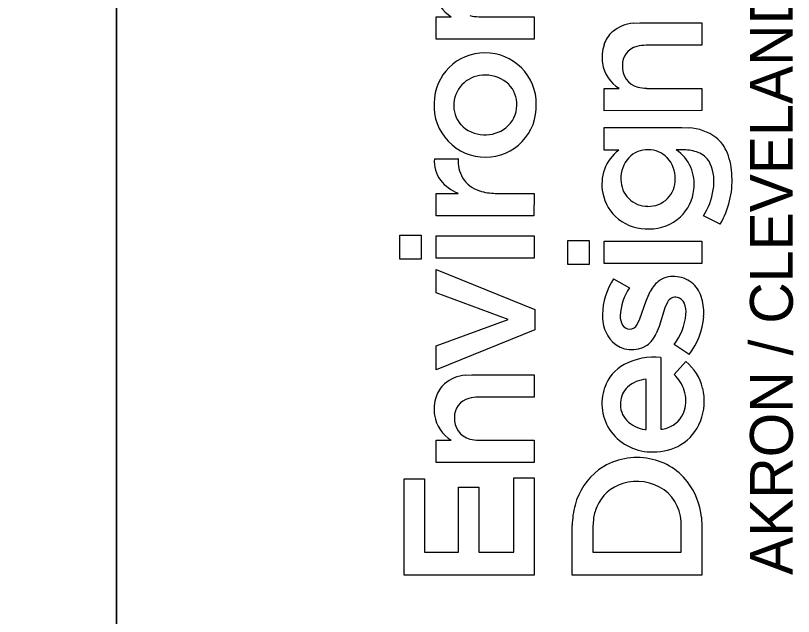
# Model space of a CAD drawing. Extents: x -0.1 to 34, y 0 to 22.
# Drawn here: x 31.866 to 32.901, y 2.583 to 3.382 of the extents above; entities that cross this region are included whole.
import ezdxf

# ---------------------------------------------------------------- set-up
doc = ezdxf.new("R2010")
doc.units = 0
for name, color, linetype in [('SH_Border', 7, 'Continuous'), ('SH_Data', 7, 'Continuous'), ('SH_Text', 7, 'Continuous')]:
    doc.layers.add(name, color=color, linetype=linetype)

msp = doc.modelspace()

# ---------------------------------------------------------------- linework, layer by layer
at = {"layer": 'SH_Border'}
msp.add_line((32, 0.5), (32, 21.5), dxfattribs=at)
at = {"layer": 'SH_Data'}
for p, q in [((32.4254, 3.3509), (32.4254, 3.3807)), ((32.4254, 3.3807), (32.4455, 3.3807)), ((32.4822, 3.3807), (32.5557, 3.3807)), ((32.5557, 3.3807), (32.5557, 3.351)), ((32.6878, 3.3722), (32.6963, 3.3727)), ((32.6963, 3.3727), (32.7792, 3.3727)), ((32.7792, 3.3727), (32.7792, 3.3429)), ((32.5557, 3.351), (32.4254, 3.3509)), ((32.7792, 3.3429), (32.7048, 3.3428)), ((32.6489, 3.2557), (32.6489, 3.2855)), ((32.6489, 3.2855), (32.669, 3.2855)), ((32.7057, 3.2855), (32.7791, 3.2855)), ((32.7791, 3.2855), (32.7792, 3.2558)), ((32.7792, 3.2558), (32.6489, 3.2557)), ((32.6489, 3.2034), (32.6489, 3.2332)), ((32.6489, 3.2332), (32.7524, 3.2332)), ((32.7524, 3.2332), (32.7619, 3.2329)), ((32.6684, 3.2034), (32.6489, 3.2034)), ((32.7576, 3.2036), (32.7449, 3.2036)), ((32.423, 3.1919), (32.4545, 3.1919)), ((32.4254, 3.1159), (32.4254, 3.1458)), ((32.4254, 3.1458), (32.4547, 3.1458)), ((32.5041, 3.1458), (32.5557, 3.1457)), ((32.5557, 3.1457), (32.5556, 3.1159)), ((32.5556, 3.1159), (32.4254, 3.1159)), ((32.8036, 3.1049), (32.7812, 3.116)), ((32.3771, 3.0582), (32.3771, 3.0903)), ((32.3771, 3.0903), (32.4054, 3.0903)), ((32.4054, 3.0903), (32.4054, 3.0582)), ((32.4254, 3.0594), (32.4254, 3.0893)), ((32.4254, 3.0893), (32.5557, 3.0893)), ((32.5557, 3.0893), (32.5557, 3.0594)), ((32.6005, 3.0511), (32.6005, 3.0832)), ((32.6005, 3.0832), (32.6289, 3.0832)), ((32.6289, 3.0832), (32.6289, 3.0511)), ((32.6489, 3.0523), (32.6489, 3.0822)), ((32.6489, 3.0822), (32.7792, 3.0822)), ((32.7792, 3.0822), (32.7792, 3.0523)), ((32.4054, 3.0582), (32.3771, 3.0582)), ((32.5557, 3.0594), (32.4254, 3.0594)), ((32.4254, 3.0133), (32.4254, 3.0446)), ((32.4254, 3.0446), (32.5567, 2.9913)), ((32.6289, 3.0511), (32.6005, 3.0511)), ((32.7792, 3.0523), (32.6489, 3.0523)), ((32.6615, 3.0321), (32.6827, 3.0203)), ((32.5212, 2.978), (32.4254, 3.0133)), ((32.7048, 3.0026), (32.7104, 3.0153)), ((32.6967, 2.9787), (32.7048, 3.0026)), ((32.7298, 2.9933), (32.7221, 2.9688)), ((32.7334, 3.001), (32.7298, 2.9933)), ((32.5567, 2.9913), (32.5567, 2.9644)), ((32.4254, 2.9429), (32.5212, 2.978)), ((32.693, 2.9712), (32.6967, 2.9787)), ((32.5567, 2.9644), (32.4254, 2.9109)), ((32.7221, 2.9688), (32.7182, 2.9592)), ((32.4254, 2.9109), (32.4254, 2.9429)), ((32.7621, 2.9314), (32.742, 2.9447)), ((32.7245, 2.9275), (32.7246, 2.8319)), ((32.7423, 2.9046), (32.7577, 2.922)), ((32.4644, 2.904), (32.4729, 2.9044)), ((32.4729, 2.9044), (32.5557, 2.9044)), ((32.5557, 2.9044), (32.5557, 2.8746)), ((32.7049, 2.8318), (32.7049, 2.8983)), ((32.5557, 2.8746), (32.4814, 2.8746)), ((32.7036, 2.8317), (32.7049, 2.8318)), ((32.4254, 2.7875), (32.4254, 2.8173)), ((32.4254, 2.8173), (32.4455, 2.8173)), ((32.4822, 2.8173), (32.5557, 2.8173)), ((32.5557, 2.8173), (32.5557, 2.7876)), ((32.5557, 2.7876), (32.4254, 2.7875)), ((32.383, 2.6379), (32.383, 2.766)), ((32.383, 2.766), (32.4101, 2.766)), ((32.4101, 2.766), (32.4101, 2.6683)), ((32.5286, 2.6683), (32.5286, 2.7672)), ((32.5286, 2.7672), (32.5557, 2.7672)), ((32.5557, 2.7672), (32.5557, 2.6379)), ((32.455, 2.6683), (32.455, 2.7549)), ((32.455, 2.7549), (32.4822, 2.7549)), ((32.4822, 2.7549), (32.4822, 2.6683)), ((32.7785, 2.715), (32.7792, 2.7021)), ((32.6064, 2.638), (32.6064, 2.704)), ((32.6347, 2.7118), (32.6341, 2.7023)), ((32.6341, 2.7023), (32.6341, 2.6684)), ((32.7515, 2.6683), (32.7515, 2.7024)), ((32.7792, 2.7021), (32.7792, 2.638)), ((32.4101, 2.6683), (32.455, 2.6683)), ((32.4822, 2.6683), (32.5286, 2.6683)), ((32.6341, 2.6684), (32.7515, 2.6683)), ((32.5557, 2.6379), (32.383, 2.6379)), ((32.7792, 2.638), (32.6064, 2.638))]:
    msp.add_line(p, q, dxfattribs=at)
for points in [[(32.4254, 3.3509), (32.4254, 3.3807), (32.4455, 3.3807)], [(32.4822, 3.3807), (32.5557, 3.3807), (32.5557, 3.351), (32.4254, 3.3509)], [(32.6878, 3.3722), (32.6963, 3.3727), (32.7792, 3.3727), (32.7792, 3.3429), (32.7048, 3.3428)], [(32.6489, 3.2557), (32.6489, 3.2855), (32.669, 3.2855)], [(32.7057, 3.2855), (32.7791, 3.2855), (32.7792, 3.2558), (32.6489, 3.2557)], [(32.6684, 3.2034), (32.6489, 3.2034), (32.6489, 3.2332), (32.7524, 3.2332), (32.7619, 3.2329)], [(32.7576, 3.2036), (32.7449, 3.2036)], [(32.423, 3.1919), (32.4545, 3.1919)], [(32.4254, 3.1159), (32.4254, 3.1458), (32.4547, 3.1458)], [(32.5041, 3.1458), (32.5557, 3.1457), (32.5556, 3.1159), (32.4254, 3.1159)], [(32.8036, 3.1049), (32.7812, 3.116)], [(32.6615, 3.0321), (32.6827, 3.0203)], [(32.693, 2.9712), (32.6967, 2.9787), (32.7048, 3.0026), (32.7104, 3.0153)], [(32.7334, 3.001), (32.7298, 2.9933), (32.7221, 2.9688), (32.7182, 2.9592)], [(32.7621, 2.9314), (32.742, 2.9447)], [(32.7245, 2.9275), (32.7246, 2.8319)], [(32.7423, 2.9046), (32.7577, 2.922)], [(32.4644, 2.904), (32.4729, 2.9044), (32.5557, 2.9044), (32.5557, 2.8746), (32.4814, 2.8746)], [(32.7036, 2.8317), (32.7049, 2.8318), (32.7049, 2.8983)], [(32.4254, 2.7875), (32.4254, 2.8173), (32.4455, 2.8173)], [(32.4822, 2.8173), (32.5557, 2.8173), (32.5557, 2.7876), (32.4254, 2.7875)], [(32.7785, 2.715), (32.7792, 2.7021), (32.7792, 2.638), (32.6064, 2.638)], [(32.6064, 2.638), (32.6064, 2.704)], [(32.6347, 2.7118), (32.6341, 2.7023), (32.6341, 2.6684), (32.7515, 2.6683), (32.7515, 2.7024)]]:
    msp.add_lwpolyline(points, dxfattribs=at)
for points in [[(32.3771, 3.0582), (32.3771, 3.0903), (32.4054, 3.0903), (32.4054, 3.0582)], [(32.4254, 3.0594), (32.4254, 3.0893), (32.5557, 3.0893), (32.5557, 3.0594)], [(32.6005, 3.0511), (32.6005, 3.0832), (32.6289, 3.0832), (32.6289, 3.0511)], [(32.6489, 3.0523), (32.6489, 3.0822), (32.7792, 3.0822), (32.7792, 3.0523)], [(32.4254, 2.9109), (32.4254, 2.9429), (32.5212, 2.978), (32.4254, 3.0133), (32.4254, 3.0446), (32.5567, 2.9913), (32.5567, 2.9644)], [(32.383, 2.6379), (32.383, 2.766), (32.4101, 2.766), (32.4101, 2.6683), (32.455, 2.6683), (32.455, 2.7549), (32.4822, 2.7549), (32.4822, 2.6683), (32.5286, 2.6683), (32.5286, 2.7672), (32.5557, 2.7672), (32.5557, 2.6379)]]:
    msp.add_lwpolyline(points, close=True, dxfattribs=at)
for centre, radius, start, end in [((32.4703, 3.4214), 0.0476, 188.9646, 238.6987), ((32.4703, 3.4214), 0.0476, 188.9646, 238.6987), ((32.4818, 3.4229), 0.0421, 254.0891, 270.5284), ((32.4818, 3.4229), 0.0421, 254.0891, 270.5284), ((32.6922, 3.3225), 0.0499, 94.9706, 130.2248), ((32.6922, 3.3225), 0.0499, 94.9706, 130.2248), ((32.6869, 3.3309), 0.0402, 132.2238, 161.6823), ((32.6869, 3.3309), 0.0402, 132.2238, 161.6823), ((32.7022, 3.3264), 0.056, 162.274, 187.7917), ((32.7022, 3.3264), 0.056, 162.274, 187.7917), ((32.6983, 3.3169), 0.025, 103.6868, 182.214), ((32.6983, 3.3169), 0.025, 103.6868, 182.214), ((32.7045, 3.2968), 0.046, 89.6051, 105.3303), ((32.7045, 3.2968), 0.046, 89.6051, 105.3303), ((32.4901, 3.2654), 0.0674, 89.8476, 179.6405), ((32.4901, 3.2654), 0.0674, 89.8476, 179.6405), ((32.4906, 3.2647), 0.0681, 359.5401, 90.2114), ((32.4906, 3.2647), 0.0681, 359.5401, 90.2114), ((32.6937, 3.3262), 0.0476, 188.9646, 238.6987), ((32.6937, 3.3262), 0.0476, 188.9646, 238.6987), ((32.7008, 3.3138), 0.0276, 175.5844, 255.1382), ((32.7008, 3.3138), 0.0276, 175.5844, 255.1382), ((32.4892, 3.2626), 0.0404, 87.0481, 175.5726), ((32.4892, 3.2626), 0.0404, 87.0481, 175.5726), ((32.492, 3.26), 0.043, 45.8426, 90.9801), ((32.492, 3.26), 0.043, 45.8426, 90.9801), ((32.4946, 3.2642), 0.0382, 357.8857, 44.159), ((32.4946, 3.2642), 0.0382, 357.8857, 44.159), ((32.7053, 3.3277), 0.0421, 254.0891, 270.5284), ((32.7053, 3.3277), 0.0421, 254.0891, 270.5284), ((32.4908, 3.2621), 0.0682, 176.8344, 270.4038), ((32.4908, 3.2621), 0.0682, 176.8344, 270.4038), ((32.4873, 3.2625), 0.0385, 175.1538, 221.1471), ((32.4873, 3.2625), 0.0385, 175.1538, 221.1471), ((32.4912, 3.2614), 0.0675, 270.0624, 2.3776), ((32.4912, 3.2614), 0.0675, 270.0624, 2.3776), ((32.4945, 3.2632), 0.0383, 308.2894, 359.4347), ((32.4945, 3.2632), 0.0383, 308.2894, 359.4347), ((32.4892, 3.2661), 0.0423, 223.0999, 268.8089), ((32.4892, 3.2661), 0.0423, 223.0999, 268.8089), ((32.491, 3.2679), 0.0442, 266.5651, 308.0608), ((32.491, 3.2679), 0.0442, 266.5651, 308.0608), ((32.7591, 3.1679), 0.065, 53.4034, 87.4906), ((32.7591, 3.1679), 0.065, 53.4034, 87.4906), ((32.7652, 3.1804), 0.0514, 21.6075, 50.5577), ((32.7652, 3.1804), 0.0514, 21.6075, 50.5577), ((32.7029, 3.1581), 0.0569, 127.3748, 192.2247), ((32.7029, 3.1581), 0.0569, 127.3748, 192.2247), ((32.7069, 3.1693), 0.0346, 88.473, 136.4256), ((32.7069, 3.1693), 0.0346, 88.473, 136.4256), ((32.7081, 3.1696), 0.0342, 44.2719, 90.4762), ((32.7081, 3.1696), 0.0342, 44.2719, 90.4762), ((32.7142, 3.1583), 0.0547, 352.1125, 55.923), ((32.7142, 3.1583), 0.0547, 352.1125, 55.923), ((32.7567, 3.1572), 0.0463, 65.0169, 88.8011), ((32.7567, 3.1572), 0.0463, 65.0169, 88.8011), ((32.7626, 3.1716), 0.0309, 26.2681, 63.803), ((32.7626, 3.1716), 0.0309, 26.2681, 63.803), ((32.7307, 3.1671), 0.0884, 1.1514, 21.3627), ((32.7307, 3.1671), 0.0884, 1.1514, 21.3627), ((32.4662, 3.1888), 0.0433, 175.8731, 216.3475), ((32.4662, 3.1888), 0.0433, 175.8731, 216.3475), ((32.5009, 3.1895), 0.0464, 176.9688, 209.6064), ((32.5009, 3.1895), 0.0464, 176.9688, 209.6064), ((32.7114, 3.166), 0.0401, 137.4674, 182.3324), ((32.7114, 3.166), 0.0401, 137.4674, 182.3324), ((32.7037, 3.166), 0.04, 358.5714, 43.5376), ((32.7037, 3.166), 0.04, 358.5714, 43.5376), ((32.7357, 3.1615), 0.0595, 349.3073, 23.4307), ((32.7357, 3.1615), 0.0595, 349.3073, 23.4307), ((32.7054, 3.1624), 0.1138, 329.6388, 3.26), ((32.7054, 3.1624), 0.1138, 329.6388, 3.26), ((32.4747, 3.1972), 0.0551, 218.0981, 248.7907), ((32.4747, 3.1972), 0.0551, 218.0981, 248.7907), ((32.4951, 3.1881), 0.0408, 211.9447, 253.2028), ((32.4951, 3.1881), 0.0408, 211.9447, 253.2028), ((32.7065, 3.1637), 0.0351, 178.8821, 271.0837), ((32.7065, 3.1637), 0.0351, 178.8821, 271.0837), ((32.7082, 3.164), 0.0355, 268.2788, 1.5502), ((32.7082, 3.164), 0.0355, 268.2788, 1.5502), ((32.5047, 3.2165), 0.0707, 252.4655, 269.573), ((32.5047, 3.2165), 0.0707, 252.4655, 269.573), ((32.7099, 3.1571), 0.0589, 313.742, 353.8554), ((32.7099, 3.1571), 0.0589, 313.742, 353.8554), ((32.7074, 3.1633), 0.0877, 327.3149, 351.5748), ((32.7074, 3.1633), 0.0877, 327.3149, 351.5748), ((32.7046, 3.157), 0.0584, 190.7518, 231.2892), ((32.7046, 3.157), 0.0584, 190.7518, 231.2892), ((32.7063, 3.1611), 0.0627, 232.4606, 272.5902), ((32.7063, 3.1611), 0.0627, 232.4606, 272.5902), ((32.7095, 3.159), 0.0605, 269.6361, 312.7088), ((32.7095, 3.159), 0.0605, 269.6361, 312.7088), ((32.7406, 3.0026), 0.0326, 80.1719, 122.5197), ((32.7406, 3.0026), 0.0326, 80.1719, 122.5197), ((32.7428, 2.9982), 0.0367, 47.7934, 84.6892), ((32.7428, 2.9982), 0.0367, 47.7934, 84.6892), ((32.7364, 2.9826), 0.0897, 146.531, 178.7571), ((32.7364, 2.9826), 0.0897, 146.531, 178.7571), ((32.7466, 2.9971), 0.0405, 125.5118, 153.4159), ((32.7466, 2.9971), 0.0405, 125.5118, 153.4159), ((32.7379, 2.9946), 0.0427, 14.9966, 46.2063), ((32.7379, 2.9946), 0.0427, 14.9966, 46.2063), ((32.7452, 2.9789), 0.0749, 146.5112, 176.9101), ((32.7452, 2.9789), 0.0749, 146.5112, 176.9101), ((32.7438, 2.9963), 0.0114, 76.6609, 155.7053), ((32.7438, 2.9963), 0.0114, 76.6609, 155.7053), ((32.744, 2.9951), 0.0126, 21.5098, 78.5262), ((32.744, 2.9951), 0.0126, 21.5098, 78.5262), ((32.7104, 2.9867), 0.0712, 355.8306, 15.3914), ((32.7104, 2.9867), 0.0712, 355.8306, 15.3914), ((32.7259, 2.9877), 0.0321, 354.5726, 22.068), ((32.7259, 2.9877), 0.0321, 354.5726, 22.068), ((32.6967, 2.9824), 0.0501, 177.5366, 222.7932), ((32.6967, 2.9824), 0.0501, 177.5366, 222.7932), ((32.6931, 2.9823), 0.0228, 178.4747, 211.0868), ((32.6931, 2.9823), 0.0228, 178.4747, 211.0868), ((32.6825, 2.9915), 0.0757, 321.811, 354.7969), ((32.6825, 2.9915), 0.0757, 321.811, 354.7969), ((32.6895, 2.9882), 0.0922, 321.9777, 355.8738), ((32.6895, 2.9882), 0.0922, 321.9777, 355.8738), ((32.6833, 2.9767), 0.0115, 212.2368, 268.3777), ((32.6833, 2.9767), 0.0115, 212.2368, 268.3777), ((32.6834, 2.9759), 0.0107, 267.716, 333.7337), ((32.6834, 2.9759), 0.0107, 267.716, 333.7337), ((32.681, 2.9758), 0.0408, 308.0877, 335.9874), ((32.681, 2.9758), 0.0408, 308.0877, 335.9874), ((32.686, 2.9753), 0.0375, 225.9854, 302.4797), ((32.686, 2.9753), 0.0375, 225.9854, 302.4797), ((32.7152, 2.8441), 0.0838, 83.615, 118.2876), ((32.7152, 2.8441), 0.0838, 83.615, 118.2876), ((32.7174, 2.8717), 0.0644, 13.5336, 51.3615), ((32.7174, 2.8717), 0.0644, 13.5336, 51.3615), ((32.7024, 2.8691), 0.0558, 118.8308, 160.6244), ((32.7024, 2.8691), 0.0558, 118.8308, 160.6244), ((32.4687, 2.8543), 0.0499, 94.9696, 130.2225), ((32.4687, 2.8543), 0.0499, 94.9696, 130.2225), ((32.7038, 2.8656), 0.0549, 19.0357, 45.4406), ((32.7038, 2.8656), 0.0549, 19.0357, 45.4406), ((32.4635, 2.8626), 0.0402, 132.2219, 161.6818), ((32.4635, 2.8626), 0.0402, 132.2219, 161.6818), ((32.7079, 2.8561), 0.0424, 94.008, 130.8817), ((32.7079, 2.8561), 0.0424, 94.008, 130.8817), ((32.7104, 2.8661), 0.0644, 160.5201, 215.7831), ((32.7104, 2.8661), 0.0644, 160.5201, 215.7831), ((32.7005, 2.8663), 0.0298, 132.9851, 177.179), ((32.7005, 2.8663), 0.0298, 132.9851, 177.179), ((32.7107, 2.8697), 0.047, 344.6059, 17.007), ((32.7107, 2.8697), 0.047, 344.6059, 17.007), ((32.7064, 2.8692), 0.0758, 339.3542, 13.3785), ((32.7064, 2.8692), 0.0758, 339.3542, 13.3785), ((32.4787, 2.8582), 0.056, 162.2736, 187.7919), ((32.4787, 2.8582), 0.056, 162.2736, 187.7919), ((32.4748, 2.8487), 0.025, 103.6865, 182.2187), ((32.4748, 2.8487), 0.025, 103.6865, 182.2187), ((32.4811, 2.8286), 0.046, 89.6049, 105.3284), ((32.4811, 2.8286), 0.046, 89.6049, 105.3284), ((32.7017, 2.865), 0.0311, 175.0013, 223.283), ((32.7017, 2.865), 0.0311, 175.0013, 223.283), ((32.4703, 2.858), 0.0476, 188.962, 238.7037), ((32.4703, 2.858), 0.0476, 188.962, 238.7037), ((32.4773, 2.8456), 0.0276, 175.5854, 255.1439), ((32.4773, 2.8456), 0.0276, 175.5854, 255.1439), ((32.7224, 2.8671), 0.035, 288.0077, 343.5508), ((32.7224, 2.8671), 0.035, 288.0077, 343.5508), ((32.7089, 2.8736), 0.0423, 225.0619, 262.7974), ((32.7089, 2.8736), 0.0423, 225.0619, 262.7974), ((32.7189, 2.8652), 0.0626, 300.9427, 338.7323), ((32.7189, 2.8652), 0.0626, 300.9427, 338.7323), ((32.7125, 2.8705), 0.0687, 217.7452, 271.6543), ((32.7125, 2.8705), 0.0687, 217.7452, 271.6543), ((32.7247, 2.8522), 0.0202, 269.7003, 294.8711), ((32.7247, 2.8522), 0.0202, 269.7003, 294.8711), ((32.4818, 2.8595), 0.0422, 254.0916, 270.5284), ((32.4818, 2.8595), 0.0422, 254.0916, 270.5284), ((32.7155, 2.8724), 0.0706, 269.2048, 300.3341), ((32.7155, 2.8724), 0.0706, 269.2048, 300.3341), ((32.6923, 2.7079), 0.0864, 81.194, 125.9984), ((32.6923, 2.7079), 0.0864, 81.194, 125.9984), ((32.6946, 2.7113), 0.0827, 37.8521, 82.402), ((32.6946, 2.7113), 0.0827, 37.8521, 82.402), ((32.6939, 2.7089), 0.0865, 127.2362, 165.148), ((32.6939, 2.7089), 0.0865, 127.2362, 165.148), ((32.6889, 2.7078), 0.054, 106.1881, 157.3861), ((32.6889, 2.7078), 0.054, 106.1881, 157.3861), ((32.6928, 2.6986), 0.0639, 55.6727, 107.2093), ((32.6928, 2.6986), 0.0639, 55.6727, 107.2093), ((32.6859, 2.7057), 0.0931, 5.7333, 37.304), ((32.6859, 2.7057), 0.0931, 5.7333, 37.304), ((32.6929, 2.705), 0.0587, 357.4662, 52.2665), ((32.6929, 2.705), 0.0587, 357.4662, 52.2665), ((32.7143, 2.7028), 0.1078, 164.7861, 179.3704), ((32.7143, 2.7028), 0.1078, 164.7861, 179.3704), ((32.6983, 2.7039), 0.0641, 157.3571, 172.9275), ((32.6983, 2.7039), 0.0641, 157.3571, 172.9275)]:
    msp.add_arc(centre, radius, start, end, dxfattribs=at)
at = {"layer": 'SH_Text'}
msp.add_lwpolyline([(32, 0.5), (1.5, 0.5), (1.5, 21.5), (32, 21.5)], close=True, dxfattribs=at)

# ---------------------------------------------------------------- texts
at = {"layer": 'SH_Data'}
msp.add_text('AKRON / CLEVELAND / COLUMBUS', height=0.056969, rotation=90, dxfattribs=at).set_placement((32.9001, 2.638))

doc.saveas('drawing.dxf')
